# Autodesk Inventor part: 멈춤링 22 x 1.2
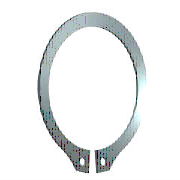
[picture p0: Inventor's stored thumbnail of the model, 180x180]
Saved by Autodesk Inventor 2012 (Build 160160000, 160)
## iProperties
IsCustomPart: 0
Company: 한국ATC센터
Created: 2014-07
Part Number: 멈춤링 22 x 1.2
Material: Steel, Mild
Description: 리테이닝 링(C형)
Document SubType Name: Modeling
Standard: KS B 1336
Designer: KYOUNG IL JANG
Standards Organization: KS
Language: ko-KR
Size Designation: 22 x 1.2
Categories: <MemberInstance><Categories><Category DisplayName="샤프트 부품" InternalName="7f7aeb1f-a693-4053-b835-cee3144e0d98" Mnemonic="SHFT"><Category DisplayName="써클립" Inter
Density: 7.86 g/cm^3
Mass: 1.82859 g
Surface Area: 5.91219 cm^2
Volume: 0.232645 cm^3
Author: KYOUNG IL JANG
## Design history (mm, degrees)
sketch "스케치1"
  geometry: L1 (-6, 0)-(6, 0) reference; L2 (0, 20.189)-(0, -80.536) reference; L3 (-48.09, 0)-(48.09, 0) reference; L4 (-0.5, -21.488)-(-0.5, -25.588); L5 (-0.5, -6.54)-(-0.5, -13.29); L6 (-2.795, 2.7)-(3.672, 2.7); L7 (0.5, -6.54)-(0.5, -13.29); L8 (0.5, -21.488)-(0.5, -25.588); C1 r 1 at (-2, -23.437); C2 r 1 at (2, -23.437); A1 r 10.5 centre (0, -11) between (0.5, -21.488) and (-0.5, -21.488); A2 r 13.025 centre (0, -10.325) between (5.149, -22.289) and (-5.149, -22.289); A3 r 14.597 centre (0, -11) between (-2.318, -25.411) and (-0.5, -25.588); A4 r 2 centre (-2, -23.437) between (-3.97, -23.781) and (-2.318, -25.411); A5 r 2 centre (-5.94, -24.126) between (-3.97, -23.781) and (-5.149, -22.289); A6 r 2 centre (5.94, -24.126) between (5.149, -22.289) and (3.97, -23.781); A7 r 2 centre (2, -23.437) between (2.318, -25.411) and (3.97, -23.781); A8 r 14.597 centre (0, -11) between (0.5, -25.588) and (2.318, -25.411)
  constraints: 16 point on circle, 12 end point, 10 centre point, 9 symmetric about line, 5 point on line, 4 tangent, 3 coincident, 2 horizontal, 1 perpendicular, 1 vertical, 5 other
  dimensions: "d0" = 21 diameter of A1 (= ND); "d1" = 4.1 distance of L4.end L4.start (= SRB2); "d6" = 0.5 distance between parallel lines of L2 L5 (= 0.25 x SD5); "d7" = 2.7 distance between parallel lines of L6 L3 (= SRB1); "d8" = 0.675 distance of A1.centre A2.centre (= 0.25 x SRB1); "d9" = 2 radius of A4 (= SD5); "d10" = 2 radius of A5 (= SD5); "d11" = 1.5 distance from line of L4 A4.centre (= 0.75 x SD5); "d12" = 2 diameter of C1 (= SD5); "d13" = 2 diameter of C2 (= SD5); "d14" = 11 distance from line of A1.centre L1 (= 0.5 x WD)
extrude "본체" new body sketch "스케치1" distance "d2" = 1.2 (= SD); taper "d3" = 0 deg
workaxis "Work Axis1"
workplane "Work Plane1"
body "Solid1"
other parameters: "WD" = 22 (= WDMIN) [user parameter; used in 1 equation term], "SD" = 1.2 [user parameter; used in 1 equation term], "SRB1" = 2.7 [user parameter; used in 2 equation terms], "ND" = 21 [user parameter; used in 1 equation term], "SRB2" = 4.1 [user parameter; used in 1 equation term], "SD5" = 2 [user parameter; used in 6 equation terms], "d15" = 0, "d16" = 0, "d17" = 0, "d41" = 0, "d42" = 0, "WDMIN" = 22 [user parameter; used in 1 equation term], "SD3" = 20.5 [user parameter], "WDMAX" = 24 [user parameter]
